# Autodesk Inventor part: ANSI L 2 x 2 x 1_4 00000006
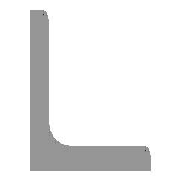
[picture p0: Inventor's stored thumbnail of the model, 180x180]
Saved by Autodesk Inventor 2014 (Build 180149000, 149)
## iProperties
_FrameMemberDoc: Frame Member File
_Version: 13.0.0
_CCFamilyMember: 11
_CCFamilyDisplayName: ANSI L (Equal angles) - Angle Steel
Created: 2007-02
Part Number: ANSI L 2 x 2 x 1_4 00000006
Material: Steel, Mild
Document SubType Name: Modeling
Standard: AISC
Designer: Autodesk, Inc.
Size Designation: L 2 x 2 x 1/4
Stock Number: L 2 x 2 x 1/4
Density: 7.86 g/cm^3
Description: Angle Steel
Standards Organization: ANSI
Language: en-US
Categories: <MemberInstance><Categories><Category DisplayName="Structural Shapes" InternalName="089c4875-fa83-4c05-b084-43b9cc11f5ed" Mnemonic="GRDR"><CategoryParameter Dis
Mass: 3370.01 g
Surface Area: 1403.81 cm^2
Volume: 428.754 cm^3
Appearance: Steel
IsCustomPart: 1
G_L: 28.000 in
G_W: 2.000 in
G_H: 2.000 in
+CC282AAB-4AD7-4025-8A75-6B04D7C1D3BB+CUTDETAIL1: Notch
+4B234BBB-5376-4DC8-859A-8989FA403DFD+CUTDETAIL2: Notch
Author: Autodesk, Inc.
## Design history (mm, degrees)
node "Start plane"
node "End plane"
sketch "Sketch"
  geometry: L1 (50.8, 0)-(0, 0); L2 (0, 0)-(0, 50.8); L3 (0, 50.8)-(3.302, 50.8); L4 (6.35, 47.752)-(6.35, 12.7); L5 (12.7, 6.35)-(47.752, 6.35); L6 (50.8, 3.302)-(50.8, 0); L7 (0, -11.041)-(0, 31.538); L8 (-11.041, 0)-(31.538, 0); L9 (0, 63.926)-(0, -23.536) reference; L10 (-23.536, 0)-(63.926, 0) reference; A1 r 6.35 centre (12.7, 12.7) between (6.35, 12.7) and (12.7, 6.35); A2 r 3.048 centre (3.302, 47.752) between (6.35, 47.752) and (3.302, 50.8); A3 r 3.048 centre (47.752, 3.302) between (50.8, 3.302) and (47.752, 6.35); 3 further points
  constraints: 16 end point, 6 point on circle, 6 point on line, 6 tangent, 4 parallel, 3 centre point, 2 collinear, 1 equal radius, 1 horizontal, 1 perpendicular
  dimensions: "d0" = 50.8 distance between parallel lines of L6 L2 (= G_H); "d1" = 50.8 distance between parallel lines of L3 L1 (= G_H); "d2" = 6.35 distance between parallel lines of L2 L4 (= G_T); "d3" = 6.35 distance between parallel lines of L1 L5 (= G_T); "d10" = 0 distance between parallel lines of L7 L2 (computed from ex); "d11" = 0 distance between parallel lines of L8 L1 (computed from d10); "d14" = 6.35 radius of A1 (= G_IR); "d15" = 3.048 radius of A2 (= G_ER)
extrude "Body" new body sketch "Sketch" stored distance "d4" = 711.2 (= G_L); taper "d5" = 0 deg
node "Driven Length"
  sketch "Sketch5"
    geometry: L1 (0, 0)-(10, 0) reference
    constraints: 2 end point, 1 horizontal
  workplane "Work Plane7"
  sketch "Sketch6"
    geometry: L1 (-2, 0)-(12, 0) reference; L2 (-2, 711.2)-(12, 711.2) reference
    dimensions: "d21" = 711.2 distance between parallel lines of L1 L2 (derived)
workplane "Work Plane3"
workplane "Work Plane4"
derived "ANSI L 2 x 2 x 1_4 00000003.ipt"
  sketch "Sketch_1"
    geometry: L1 (50.8, 0)-(0, 0) reference; L2 (0, 0)-(0, 50.8) reference; L3 (0, 50.8)-(3.302, 50.8) reference; L4 (6.35, 47.752)-(6.35, 12.7) reference; L5 (12.7, 6.35)-(47.752, 6.35) reference; L6 (50.8, 3.302)-(50.8, 0) reference; L7 (0, -11.041)-(0, 31.538) reference; L8 (-11.041, 0)-(31.538, 0) reference; L9 (0, 63.926)-(0, -23.536) reference; L10 (-23.536, 0)-(63.926, 0) reference; A1 r 6.35 centre (12.7, 12.7) between (6.35, 12.7) and (12.7, 6.35) reference; A2 r 3.048 centre (3.302, 47.752) between (6.35, 47.752) and (3.302, 50.8) reference; A3 r 3.048 centre (47.752, 3.302) between (50.8, 3.302) and (47.752, 6.35) reference; 3 further points
extrude "Extrusion2" cut sketch "Sketch_1" stored distance "d16" = 3.302; taper "d17" = 0 deg
workplane "Work Plane5"
workplane "Work Plane6"
derived "ANSI L 2 x 2 x 1_4 00000004.ipt"
  sketch "Sketch_2"
    geometry: L1 (50.8, 0)-(0, 0) reference; L2 (0, 0)-(0, 50.8) reference; L3 (0, 50.8)-(3.302, 50.8) reference; L4 (6.35, 47.752)-(6.35, 12.7) reference; L5 (12.7, 6.35)-(47.752, 6.35) reference; L6 (50.8, 3.302)-(50.8, 0) reference; L7 (0, -11.041)-(0, 31.538) reference; L8 (-11.041, 0)-(31.538, 0) reference; L9 (0, 63.926)-(0, -23.536) reference; L10 (-23.536, 0)-(63.926, 0) reference; A1 r 6.35 centre (12.7, 12.7) between (6.35, 12.7) and (12.7, 6.35) reference; A2 r 3.048 centre (3.302, 47.752) between (6.35, 47.752) and (3.302, 50.8) reference; A3 r 3.048 centre (47.752, 3.302) between (50.8, 3.302) and (47.752, 6.35) reference; 3 further points
extrude "Extrusion3" cut sketch "Sketch_2" stored distance "d18" = 3.302; taper "d19" = 0 deg
body "Solid1"
other parameters: "G_H" = 50.8 [user parameter; used in 2 equation terms], "G_T" = 6.35 [user parameter; used in 2 equation terms], "G_ER" = 3.048 [user parameter; used in 1 equation term], "G_IR" = 6.35 [user parameter; used in 1 equation term], "G_L" = 711.2 (= d21) [user parameter; used in 1 equation term], "ex" = 0 [user parameter; used in 1 equation term], "G_OFFSET_START" = 0 [user parameter; used in 1 equation term], "G_OFFSET_END" = 0 [user parameter; used in 1 equation term], "d12" = 0 (computed from G_OFFSET_START), "d13" = 711.2 (= G_OFFSET_END + B_L), "B_L" = 711.2 [user parameter; used in 1 equation term], "d20" = 90 deg
